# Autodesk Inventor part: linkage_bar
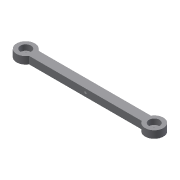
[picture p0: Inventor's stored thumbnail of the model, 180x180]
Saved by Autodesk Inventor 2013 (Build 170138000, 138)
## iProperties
Created: 2013-11
Part Number: linkage_bar
Material: Generic
Document SubType Name: Modeling
Designer: Jonas
Density: 1 g/cm^3
Author: Jonas
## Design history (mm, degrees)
sketch "Sketch1"
  geometry: L1 (0, 2.5)-(0, -2.5); L2 (0, 2.5)-(-30.67, 2.5); L3 (0, -2.5)-(-30.67, -2.5); A1 r 5 centre (-35, 0) between (-30.67, 2.5) and (-30.67, -2.5); 2 further points
  constraints: 6 end point, 2 coincident, 2 point on circle, 1 centre point, 1 horizontal alignment, 1 midpoint, 1 parallel, 1 perpendicular, 1 vertical
  dimensions: "d0" = 10 diameter of A1; "d1" = 5 distance between parallel lines of L3 L2; "d2" = 35 distance from line of L1 A1.centre
extrude "Extrusion1" new body sketch "Sketch1" distance "d3" = 4; taper "d4" = 0 deg
sketch "Sketch2"
  geometry: A1 r 5 centre (-35, 0) between (-30.67, 2.5) and (-30.67, -2.5) reference; 2 further points
  constraints: 1 coincident
hole "Hole1" sketch "Sketch2" at (-35, 0) diameter "d5" = 3; stored, may be unused: countersink angle "d9" = 90 deg, drill point angle "d11" = 118 deg; dims "d6" = 6, "d7" = 5.8, "d8" = 3, "d10" = 8
sketch "Sketch3"
  geometry: L1 (30.67, 0)-(30.67, 4) reference; L2 (30.67, 2.671)-(29.87, 2); L3 (29.87, 2)-(30.67, 1.329); L4 (30.67, 2.671)-(30.67, 1.329); L5 (30.67, 0)-(0, 0) reference; 2 further points
  constraints: 6 end point, 2 midpoint, 2 point on line, 1 coincident, 1 collinear, 1 equal length
  dimensions: "d12" = 0.8 distance of point (30.67, 2) L2.end; "d16" = 40 deg angle of L5 L2
extrude "Extrusion2" cut sketch "Sketch3" stored distance "d14" = 4; taper "d15" = 0 deg
mirror "Mirror1"
body "Solid1"
